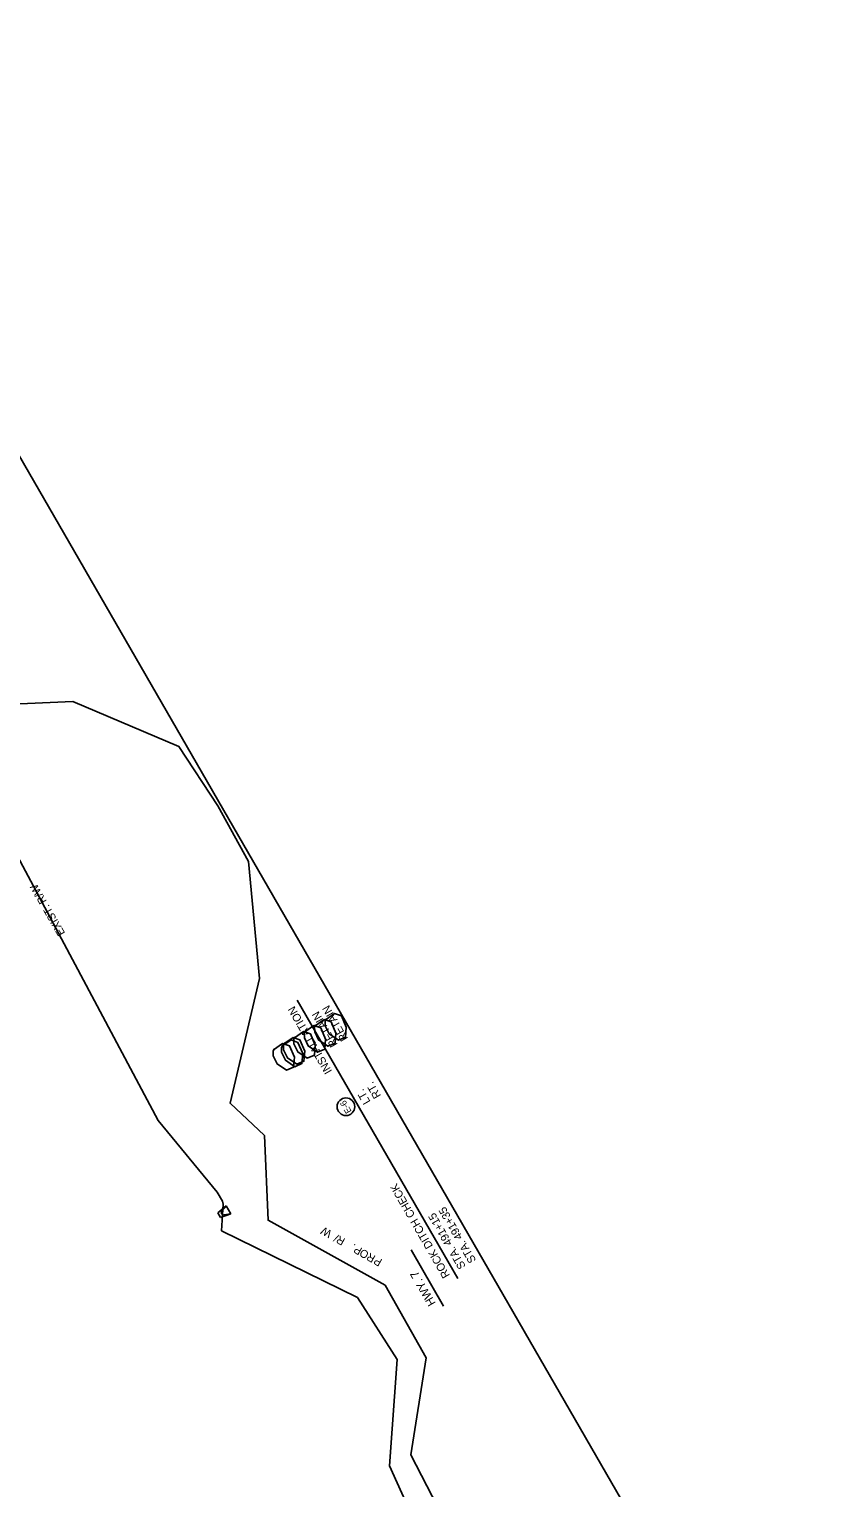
# Model space of a CAD drawing. Extents: x 956270 to 957915, y 1920520 to 1922423.
# Drawn here: x 957310 to 957915, y 1921329 to 1922423 of the extents above; entities that cross this region are included whole.
import ezdxf

# ---------------------------------------------------------------- set-up
doc = ezdxf.new("R2010")
doc.units = 0
for name, color, linetype in [('1', 7, 'Continuous'), ('44', 7, 'Continuous'), ('NO PLOT', 7, 'Continuous'), ('R_Draft', 7, 'Continuous'), ('R_Drainage', 7, 'Continuous'), ('S_TREE', 7, 'Continuous')]:
    doc.layers.add(name, color=color, linetype=linetype)

msp = doc.modelspace()

# ---------------------------------------------------------------- linework, layer by layer
at = {"layer": '1'}
msp.add_circle((957547.6, 1921615.1), 6.61, dxfattribs=at)
at = {"layer": '44'}
for p, q in [((957631.5, 1921486.3), (957511, 1921695)), ((957620.9, 1921465.5), (957596.5, 1921507.8))]:
    msp.add_line(p, q, dxfattribs=at)
at = {"layer": 'NO PLOT'}
msp.add_lwpolyline([(957915.2, 1921041.6), (957117.5, 1922423.2), (956666.2, 1922162.6), (956816.7, 1921902), (956875.1, 1921935.7), (957087.6, 1921567.7), (957029.2, 1921533.9), (957172.3, 1921286.1), (957225.7, 1921317), (957397.1, 1921020.2), (957343.6, 1920989.3), (957463.8, 1920781)], close=True, dxfattribs=at)
msp.add_lwpolyline([(957915.2, 1921041.6), (957117.5, 1922423.2), (956666.2, 1922162.6), (956816.7, 1921902), (956875.1, 1921935.7), (957087.6, 1921567.7), (957029.2, 1921533.9), (957172.3, 1921286.1), (957225.7, 1921317), (957397.1, 1921020.2), (957343.6, 1920989.3), (957463.8, 1920781)], close=True, dxfattribs=at)
msp.add_lwpolyline([(957915.2, 1921041.6), (957117.5, 1922423.2), (956666.2, 1922162.6), (956816.7, 1921902), (956875.1, 1921935.7), (957087.6, 1921567.7), (957029.2, 1921533.9), (957172.3, 1921286.1), (957225.7, 1921317), (957397.1, 1921020.2), (957343.6, 1920989.3), (957463.8, 1920781)], close=True, dxfattribs=at)
msp.add_lwpolyline([(957915.2, 1921041.6), (957117.5, 1922423.2), (956666.2, 1922162.6), (956816.7, 1921902), (956875.1, 1921935.7), (957087.6, 1921567.7), (957029.2, 1921533.9), (957172.3, 1921286.1), (957225.7, 1921317), (957397.1, 1921020.2), (957343.6, 1920989.3), (957463.8, 1920781)], close=True, dxfattribs=at)
for points in [[(957704.5, 1921144.2), (957596.2, 1921354.1), (957607.9, 1921426.9), (957577.1, 1921481.2), (957489.2, 1921530), (957486.5, 1921593.6), (957460.7, 1921617.7), (957482.7, 1921711.3), (957474.6, 1921798.9), (957451.4, 1921840.8), (957422.3, 1921885.2), (957342.6, 1921919), (957257.4, 1921915.2)], [(957259.1, 1921881.5), (957406.6, 1921604.7), (957451, 1921550.9), (957455.1, 1921544.3), (957455.6, 1921541.9), (957454.3, 1921522.1), (957556.2, 1921472.1), (957586, 1921425.6), (957580.2, 1921345.8), (957625.4, 1921246.1)]]:
    msp.add_lwpolyline(points, dxfattribs=at)
at = {"layer": 'R_Drainage'}
for p, q in [((957451.4, 1921535.4), (957457.8, 1921540.8)), ((957453.4, 1921532), (957451.4, 1921535.4)), ((957453.4, 1921532), (957461.3, 1921534.8)), ((957454.5, 1921536.9), (957457.8, 1921540.8)), ((957456.2, 1921533.9), (957461.3, 1921534.8)), ((957461.3, 1921534.8), (957457.8, 1921540.8))]:
    msp.add_line(p, q, dxfattribs=at)
msp.add_arc((957455.9, 1921535.7), 1.83, 140.3153, 279.6781, dxfattribs=at)
at = {"layer": 'S_TREE'}
for points in [[(957516.7, 1921671.3), (957523.5, 1921676), (957528.7, 1921674.2), (957532.3, 1921665.8), (957531.7, 1921658.2), (957526.3, 1921656), (957519.3, 1921660.7), (957516.4, 1921666.8), (957516.3, 1921670.5), (957517.3, 1921671.9)], [(957516.7, 1921671.3), (957523.5, 1921676), (957528.7, 1921674.2), (957532.3, 1921665.8), (957531.7, 1921658.2), (957526.3, 1921656), (957519.3, 1921660.7), (957516.4, 1921666.8), (957516.3, 1921670.5), (957517.3, 1921671.9)], [(957516.7, 1921671.3), (957523.5, 1921676), (957528.7, 1921674.2), (957532.3, 1921665.8), (957531.7, 1921658.2), (957526.3, 1921656), (957519.3, 1921660.7), (957516.4, 1921666.8), (957516.3, 1921670.5), (957517.3, 1921671.9)], [(957516.7, 1921671.3), (957523.5, 1921676), (957528.7, 1921674.2), (957532.3, 1921665.8), (957531.7, 1921658.2), (957526.3, 1921656), (957519.3, 1921660.7), (957516.4, 1921666.8), (957516.3, 1921670.5), (957517.3, 1921671.9)], [(957516.7, 1921671.3), (957523.5, 1921676), (957528.7, 1921674.2), (957532.3, 1921665.8), (957531.7, 1921658.2), (957526.3, 1921656), (957519.3, 1921660.7), (957516.4, 1921666.8), (957516.3, 1921670.5), (957517.3, 1921671.9)], [(957516.7, 1921671.3), (957523.5, 1921676), (957528.7, 1921674.2), (957532.3, 1921665.8), (957531.7, 1921658.2), (957526.3, 1921656), (957519.3, 1921660.7), (957516.4, 1921666.8), (957516.3, 1921670.5), (957517.3, 1921671.9)], [(957524.5, 1921675.8), (957531.2, 1921680.5), (957536.5, 1921678.7), (957540.1, 1921670.3), (957539.5, 1921662.7), (957534.1, 1921660.5), (957527.1, 1921665.2), (957524.2, 1921671.3), (957524.1, 1921675), (957525.1, 1921676.4)], [(957524.5, 1921675.8), (957531.2, 1921680.5), (957536.5, 1921678.7), (957540.1, 1921670.3), (957539.5, 1921662.7), (957534.1, 1921660.5), (957527.1, 1921665.2), (957524.2, 1921671.3), (957524.1, 1921675), (957525.1, 1921676.4)], [(957524.5, 1921675.8), (957531.2, 1921680.5), (957536.5, 1921678.7), (957540.1, 1921670.3), (957539.5, 1921662.7), (957534.1, 1921660.5), (957527.1, 1921665.2), (957524.2, 1921671.3), (957524.1, 1921675), (957525.1, 1921676.4)], [(957532.3, 1921680.3), (957539, 1921685), (957544.3, 1921683.2), (957547.9, 1921674.8), (957547.3, 1921667.2), (957541.9, 1921665), (957534.9, 1921669.7), (957531.9, 1921675.8), (957531.9, 1921679.5), (957532.9, 1921680.9)], [(957532.3, 1921680.3), (957539, 1921685), (957544.3, 1921683.2), (957547.9, 1921674.8), (957547.3, 1921667.2), (957541.9, 1921665), (957534.9, 1921669.7), (957531.9, 1921675.8), (957531.9, 1921679.5), (957532.9, 1921680.9)], [(957499.6, 1921660.4), (957506.4, 1921665.2), (957511.6, 1921663.3), (957515.2, 1921655), (957514.6, 1921647.4), (957509.2, 1921645.1), (957502.2, 1921649.9), (957499.3, 1921655.9), (957499.2, 1921659.6), (957500.2, 1921661)], [(957501.1, 1921662.3), (957507.9, 1921667), (957513.1, 1921665.2), (957516.7, 1921656.8), (957516.1, 1921649.2), (957510.7, 1921647), (957503.7, 1921651.7), (957500.8, 1921657.8), (957500.7, 1921661.5), (957501.7, 1921662.9)], [(957501.1, 1921662.3), (957507.9, 1921667), (957513.1, 1921665.2), (957516.7, 1921656.8), (957516.1, 1921649.2), (957510.7, 1921647), (957503.7, 1921651.7), (957500.8, 1921657.8), (957500.7, 1921661.5), (957501.7, 1921662.9)], [(957501.1, 1921662.3), (957507.9, 1921667), (957513.1, 1921665.2), (957516.7, 1921656.8), (957516.1, 1921649.2), (957510.7, 1921647), (957503.7, 1921651.7), (957500.8, 1921657.8), (957500.7, 1921661.5), (957501.7, 1921662.9)], [(957501.1, 1921662.3), (957507.9, 1921667), (957513.1, 1921665.2), (957516.7, 1921656.8), (957516.1, 1921649.2), (957510.7, 1921647), (957503.7, 1921651.7), (957500.8, 1921657.8), (957500.7, 1921661.5), (957501.7, 1921662.9)], [(957501.1, 1921662.3), (957507.9, 1921667), (957513.1, 1921665.2), (957516.7, 1921656.8), (957516.1, 1921649.2), (957510.7, 1921647), (957503.7, 1921651.7), (957500.8, 1921657.8), (957500.7, 1921661.5), (957501.7, 1921662.9)], [(957508.9, 1921666.8), (957515.7, 1921671.5), (957520.9, 1921669.7), (957524.5, 1921661.3), (957523.9, 1921653.7), (957518.5, 1921651.5), (957511.5, 1921656.2), (957508.6, 1921662.3), (957508.5, 1921666), (957509.5, 1921667.4)], [(957508.9, 1921666.8), (957515.7, 1921671.5), (957520.9, 1921669.7), (957524.5, 1921661.3), (957523.9, 1921653.7), (957518.5, 1921651.5), (957511.5, 1921656.2), (957508.6, 1921662.3), (957508.5, 1921666), (957509.5, 1921667.4)], [(957508.9, 1921666.8), (957515.7, 1921671.5), (957520.9, 1921669.7), (957524.5, 1921661.3), (957523.9, 1921653.7), (957518.5, 1921651.5), (957511.5, 1921656.2), (957508.6, 1921662.3), (957508.5, 1921666), (957509.5, 1921667.4)], [(957508.9, 1921666.8), (957515.7, 1921671.5), (957520.9, 1921669.7), (957524.5, 1921661.3), (957523.9, 1921653.7), (957518.5, 1921651.5), (957511.5, 1921656.2), (957508.6, 1921662.3), (957508.5, 1921666), (957509.5, 1921667.4)], [(957493.3, 1921657.8), (957500.1, 1921662.5), (957505.3, 1921660.7), (957509, 1921652.3), (957508.3, 1921644.7), (957502.9, 1921642.5), (957495.9, 1921647.2), (957493, 1921653.3), (957492.9, 1921657), (957493.9, 1921658.4)], [(957493.3, 1921657.8), (957500.1, 1921662.5), (957505.3, 1921660.7), (957509, 1921652.3), (957508.3, 1921644.7), (957502.9, 1921642.5), (957495.9, 1921647.2), (957493, 1921653.3), (957492.9, 1921657), (957493.9, 1921658.4)], [(957493.3, 1921657.8), (957500.1, 1921662.5), (957505.3, 1921660.7), (957509, 1921652.3), (957508.3, 1921644.7), (957502.9, 1921642.5), (957495.9, 1921647.2), (957493, 1921653.3), (957492.9, 1921657), (957493.9, 1921658.4)]]:
    msp.add_lwpolyline(points, dxfattribs=at)

# ---------------------------------------------------------------- texts
at = {"layer": '1'}
msp.add_text('E-6 ', height=4.8, rotation=120, dxfattribs=at).set_placement((957552, 1921611.7))
at = {"layer": '44'}
for s, height, p in [('INSTALLATION', 6, (957537.4, 1921641.7)), ('RETAIN', 6, (957541.6, 1921661.8)), ('RETAIN', 6, (957549.4, 1921666.3)), ('RT.', 6, (957574.1, 1921623.3)), ('LT.', 6, (957566.2, 1921618.9)), ('ROCK DITCH CHECK', 6, (957625.8, 1921488.6)), ('STA. 491+15', 6, (957637.7, 1921495.4)), ('STA. 491+35', 6, (957645.5, 1921499.9)), ('HWY. 7', 6.25, (957615.2, 1921467.8))]:
    msp.add_text(s, height=height, rotation=120, dxfattribs=at).set_placement(p)
at = {"layer": 'R_Draft'}
for s, rotation, p in [('EXIST. R/W', 119.9486, (957337.1, 1921745.3)), ('W', 150.5183, (957537.6, 1921521.6)), ('/', 150.5183, (957542.7, 1921518.7)), ('R', 150.5183, (957547.6, 1921515.9)), ('.', 150.5183, (957555.4, 1921511.5)), ('P', 150.5183, (957560.3, 1921508.7)), ('O', 150.5183, (957565.4, 1921505.8)), ('R', 150.5183, (957570.3, 1921503)), ('P', 150.5183, (957575.3, 1921500.2))]:
    msp.add_text(s, height=6, rotation=rotation, dxfattribs=at).set_placement(p)

doc.saveas('drawing.dxf')
